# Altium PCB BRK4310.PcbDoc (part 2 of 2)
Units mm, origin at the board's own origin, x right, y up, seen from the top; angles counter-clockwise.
Board outline 150 x 90 mm, 2 copper layers (Top Layer, Bottom Layer), stack 1.646 mm thick; 21 components, 213 nets, 662 pads, 124 vias.
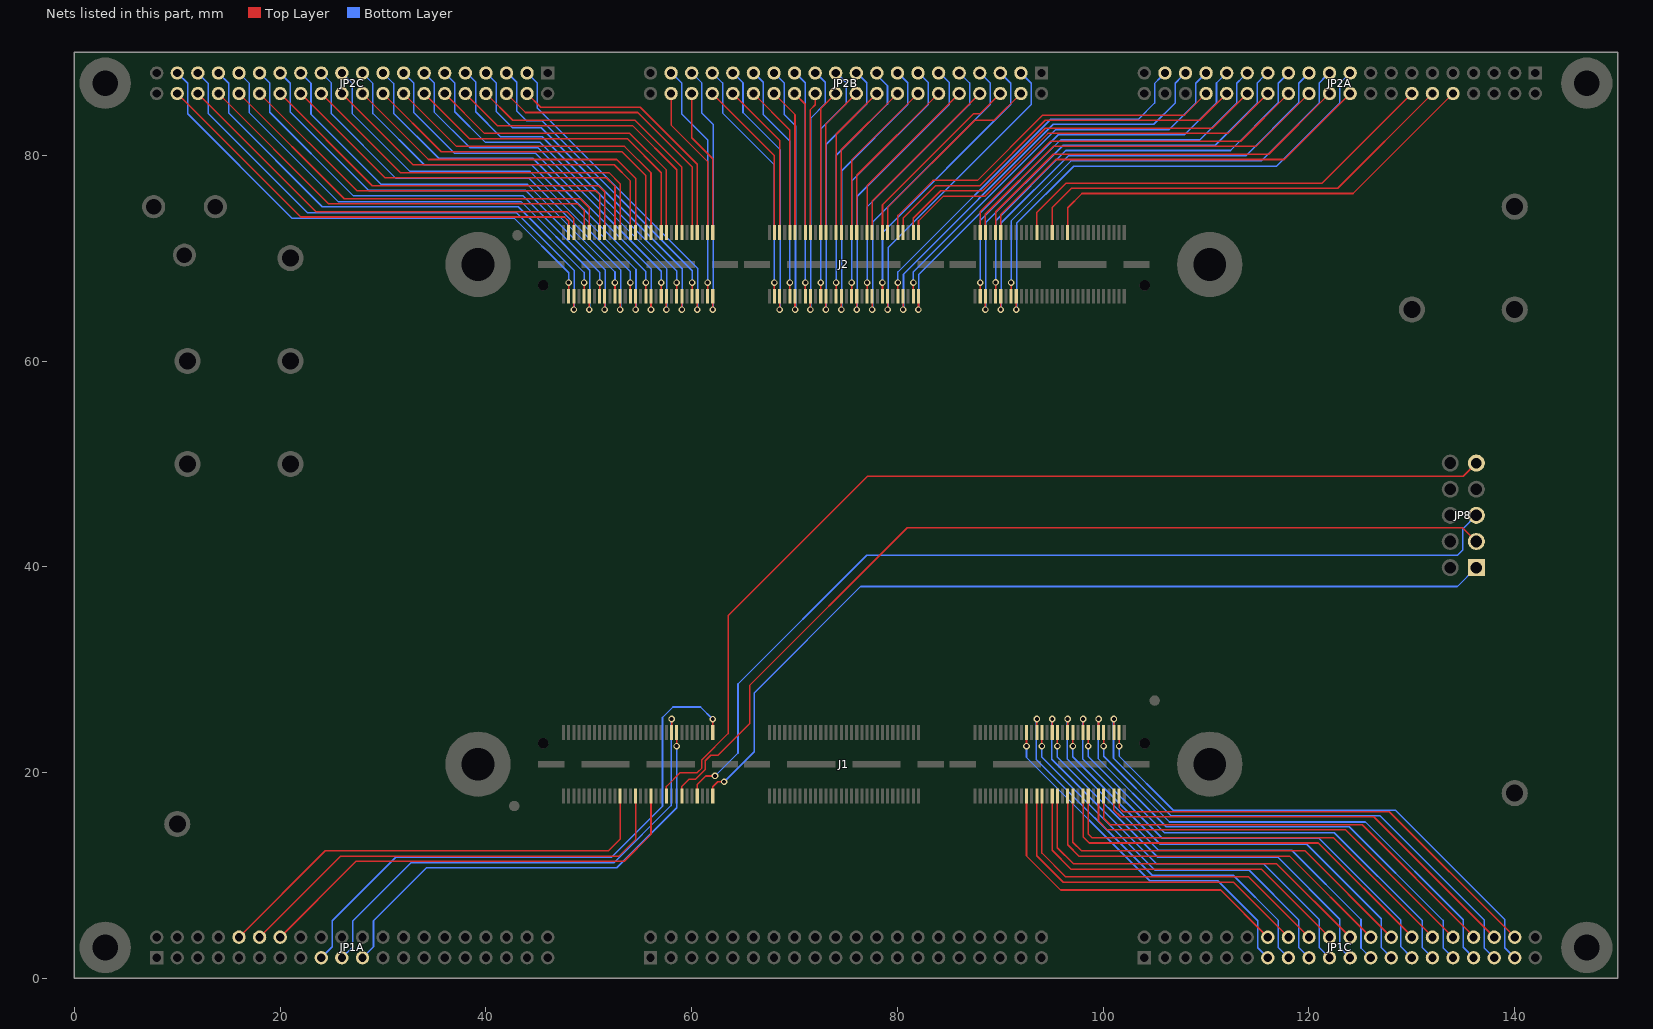
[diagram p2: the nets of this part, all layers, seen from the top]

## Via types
v1: diameter 0.635, hole 0.381, Top Layer to Bottom Layer, tented both sides, 112 vias
v2: diameter 0.889, hole 0.508, Top Layer to Bottom Layer, tented both sides, 12 vias

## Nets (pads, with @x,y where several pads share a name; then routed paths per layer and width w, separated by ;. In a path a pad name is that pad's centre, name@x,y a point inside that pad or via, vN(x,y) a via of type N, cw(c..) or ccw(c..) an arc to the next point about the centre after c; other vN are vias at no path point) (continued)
J1_141: J1.141 JP1C.13 | length 35.5
  Top Layer w0.152: v1(92.545,22.573) J1.141@92.545,23.905
  Bottom Layer w0.152: v1(92.545,22.573) 92.545,21.471 104.534,9.482 111.138,9.482 115.024,5.596 115.024,2.976 JP1C.13@116,2
J1_142: J1.142 JP1C.14 | length 32.6
  Top Layer w0.152: J1.142@92.545,17.725 92.545,11.893 95.856,8.582 111.418,8.582 JP1C.14@116,4
J1_145: J1.145 JP1C.15 | length 39.3
  Top Layer w0.152: J1.145@93.545,23.905 v1(93.545,25.206)
  Bottom Layer w0.152: v1(93.545,25.206) 93.499,25.16 93.499,21.279 104.763,10.015 112.637,10.015 117.031,5.621 117.031,2.969 JP1C.15@118,2
J1_146: J1.146 JP1C.16 | length 33.5
  Top Layer w0.152: J1.146@93.545,17.725 93.545,11.909 96.11,9.344 112.656,9.344 JP1C.16@118,4
J1_147: J1.147 JP1C.17 | length 38
  Top Layer w0.152: v1(94.045,22.573) J1.147@94.045,23.905
  Bottom Layer w0.152: v1(94.045,22.573) 94.045,21.495 105.042,10.498 114.186,10.498 118.987,5.697 118.987,3.013 JP1C.17@120,2
J1_148: J1.148 JP1C.18 | length 34.9
  Top Layer w0.152: J1.148@94.045,17.725 94.045,12.171 96.364,9.852 114.148,9.852 JP1C.18@120,4
J1_151: J1.151 JP1C.19 | length 41.8
  Top Layer w0.152: J1.151@95.045,23.905 v1(95.045,25.206)
  Bottom Layer w0.152: v1(95.045,25.206) 94.999,25.16 94.999,21.303 105.169,11.133 115.583,11.133 120.993,5.723 120.993,3.007 JP1C.19@122,2
J1_152: J1.152 JP1C.20 | length 35.7
  Top Layer w0.152: J1.152@95.045,17.725 95.045,12.441 96.872,10.614 115.386,10.614 JP1C.20@122,4
J1_153: J1.153 JP1C.21 | length 40.5
  Top Layer w0.152: v1(95.545,22.573) J1.153@95.545,23.905
  Bottom Layer w0.152: v1(95.545,22.573) 95.545,21.519 105.296,11.768 116.98,11.768 123,5.748 123,3 JP1C.21@124,2
J1_154: J1.154 JP1C.22 | length 37.1
  Top Layer w0.152: J1.154@95.545,17.725 95.545,12.703 97.126,11.122 116.878,11.122 JP1C.22@124,4
J1_157: J1.157 JP1C.23 | length 44.3
  Top Layer w0.152: J1.157@96.545,23.905 v1(96.545,25.206)
  Bottom Layer w0.152: v1(96.545,25.206) 96.499,25.16 96.499,21.327 105.372,12.454 118.326,12.454 125.057,5.723 125.057,2.943 JP1C.23@126,2
J1_158: J1.158 JP1C.24 | length 37.9
  Top Layer w0.152: J1.158@96.545,17.725 96.545,12.973 97.634,11.884 118.116,11.884 JP1C.24@126,4
J1_159: J1.159 JP1C.25 | length 43.1
  Top Layer w0.152: v1(97.045,22.573) J1.159@97.045,23.905
  Bottom Layer w0.152: v1(97.045,22.573) 97.045,21.543 105.55,13.038 119.774,13.038 127.013,5.799 127.013,2.987 JP1C.25@128,2
J1_160: J1.160 JP1C.26 | length 39.3
  Top Layer w0.152: J1.160@97.045,17.725 97.045,13.235 97.888,12.392 119.608,12.392 JP1C.26@128,4
J1_163: J1.163 JP1C.27 | length 46.7
  Top Layer w0.152: J1.163@98.045,23.905 v1(98.045,25.206)
  Bottom Layer w0.152: v1(98.045,25.206) 97.999,25.16 97.999,21.351 105.728,13.622 120.968,13.622 128.918,5.672 128.918,3.082 JP1C.27@130,2
J1_164: J1.164 JP1C.28 | length 39.6
  Top Layer w0.152: J1.164@98.045,17.725 98.045,13.759 98.65,13.154 120.903,13.154 129.59,4.467 JP1C.28@129.59,4.2
J1_165: J1.165 JP1C.29 | length 45.4
  Top Layer w0.152: v1(98.545,22.573) J1.165@98.545,23.905
  Bottom Layer w0.152: v1(98.545,22.573) 98.545,21.567 105.956,14.156 122.466,14.156 131.001,5.621 131.001,2.999 JP1C.29@132,2
J1_166: J1.166 JP1C.30 | length 41
  Top Layer w0.152: J1.166@98.545,17.725 98.545,14.021 98.904,13.662 122.376,13.662 131.59,4.448 JP1C.30@131.59,4.2
J1_169: J1.169 JP1C.31 | length 49.2
  Top Layer w0.152: J1.169@99.545,23.905 v1(99.545,25.206)
  Bottom Layer w0.152: v1(99.545,25.206) 99.499,25.16 99.499,21.375 106.134,14.74 123.914,14.74 133.033,5.621 133.033,2.967 JP1C.31@134,2
J1_170: J1.170 JP1C.32 | length 41.6
  Top Layer w0.152: J1.170@99.545,17.725 99.545,15.307 100.428,14.424 123.576,14.424 JP1C.32@134,4
J1_171: J1.171 JP1C.33 | length 48
  Top Layer w0.152: v1(100.045,22.573) J1.171@100.045,23.905
  Bottom Layer w0.152: v1(100.045,22.573) 100.045,21.591 106.439,15.197 125.489,15.197 134.989,5.697 134.989,3.011 JP1C.33@136,2
J1_172: J1.172 JP1C.34 | length 42.6
  Top Layer w0.152: J1.172@100.045,17.725 100.045,15.569 100.682,14.932 125.17,14.932 135.59,4.512 JP1C.34@135.59,4.2
J1_175: J1.175 JP1C.35 | length 51.8
  Top Layer w0.152: J1.175@101.045,23.905 v1(101.045,25.206)
  Bottom Layer w0.152: v1(101.045,25.206) 100.999,25.16 100.999,21.399 106.617,15.781 126.937,15.781 137.046,5.672 137.046,2.954 JP1C.35@138,2
J1_176: J1.176 JP1C.36 | length 43.4
  Top Layer w0.152: J1.176@101.045,17.725 101.045,16.347 101.698,15.694 126.306,15.694 JP1C.36@138,4
J1_177: J1.177 JP1C.37 | length 50.5
  Top Layer w0.152: v1(101.545,22.573) J1.177@101.545,23.905
  Bottom Layer w0.152: v1(101.545,22.573) 101.545,21.615 106.82,16.34 128.41,16.34 139.027,5.723 139.027,2.973 JP1C.37@140,2
J1_178: J1.178 JP1C.38 | length 44.4
  Top Layer w0.152: J1.178@101.545,17.725 101.545,16.609 101.952,16.202 127.811,16.202 139.59,4.423 JP1C.38@139.59,4.2
J2_49: J2.49 JP2A.23 | length 46.8
  Top Layer w0.152: v1(90.045,64.992) J2.49@90.045,66.295
  Bottom Layer w0.152: v1@90.091,65.058 90.091,73.429 96.618,79.956 113.869,79.956 119.012,85.099 119.012,87.003 119.59,87.581 JP2A.23@119.59,88.2
J2_50: J2.50 JP2A.20 | length 40.6
  Top Layer w0.152: J2.50@90.045,72.475 90.045,74.241 95.39,79.586 117.586,79.586 JP2A.20@124,86
J2_51: J2.51 JP2A.25 | length 42.9
  Top Layer w0.152: J2.51@89.545,66.295 v1(89.545,67.645)
  Bottom Layer w0.152: v1(89.545,67.645) 89.545,73.645 96.364,80.464 112.377,80.464 117.005,85.092 117.005,87.003 117.59,87.587 JP2A.25@117.59,88.2
J2_52: J2.52 JP2A.22 | length 39.2
  Top Layer w0.152: J2.52@89.545,72.475 89.545,74.503 95.136,80.094 116.094,80.094 JP2A.22@122,86
J2_55: J2.55 JP2A.27 | length 44.3
  Top Layer w0.152: v1(88.545,64.994) J2.55@88.545,66.295
  Bottom Layer w0.152: v1@88.591,65.04 88.591,73.453 96.11,80.972 110.885,80.972 114.973,85.06 114.973,87.028 115.59,87.645 JP2A.27@115.59,88.2
J2_56: J2.56 JP2A.24 | length 38.1
  Top Layer w0.152: J2.56@88.545,72.475 88.545,74.265 95.136,80.856 114.856,80.856 JP2A.24@120,86
J2_57: J2.57 JP2A.29 | length 40.4
  Top Layer w0.152: J2.57@88.045,66.295 v1(88.045,67.627)
  Bottom Layer w0.152: v1(88.045,67.627) 88.045,73.669 95.856,81.48 109.393,81.48 112.992,85.079 112.992,87.003 113.59,87.601 JP2A.29@113.59,88.2
J2_58: J2.58 JP2A.26 | length 36.8
  Top Layer w0.152: J2.58@88.045,72.475 88.045,74.527 94.882,81.364 113.364,81.364 JP2A.26@118,86
J2_61: J2.61 JP2A.31 | length 43.9
  Top Layer w0.152: v1(82.045,64.994) J2.61@82.045,66.295
  Bottom Layer w0.152: v1@82.091,65.04 82.091,68.439 95.64,81.988 107.901,81.988 111.011,85.098 111.011,87.028 111.59,87.607 JP2A.31@111.59,88.2
J2_62: J2.62 JP2A.28 | length 40.2
  Top Layer w0.152: J2.62@82.045,72.475 82.045,73.607 84.468,76.03 88.532,76.03 94.628,82.126 112.126,82.126 JP2A.28@116,86
J2_63: J2.63 JP2A.33 | length 40
  Top Layer w0.152: J2.63@81.545,66.295 v1(81.545,67.627)
  Bottom Layer w0.152: v1(81.545,67.627) 81.545,68.651 95.39,82.496 106.409,82.496 109.004,85.091 109.004,87.003 109.59,87.588 JP2A.33@109.59,88.2
J2_64: J2.64 JP2A.30 | length 38.9
  Top Layer w0.152: J2.64@81.545,72.475 81.545,73.869 84.214,76.538 88.278,76.538 94.374,82.634 110.634,82.634 JP2A.30@114,86
J2_67: J2.67 JP2A.35 | length 41.4
  Top Layer w0.152: v1(80.545,64.994) J2.67@80.545,66.295
  Bottom Layer w0.152: v1@80.591,65.04 80.591,68.439 95.156,83.004 104.917,83.004 106.998,85.085 106.998,87.003 107.59,87.595 JP2A.35@107.59,88.2
J2_68: J2.68 JP2A.32 | length 37.9
  Top Layer w0.152: J2.68@80.545,72.475 80.545,73.885 83.706,77.046 88.024,77.046 94.374,83.396 109.396,83.396 JP2A.32@112,86
J2_69: J2.69 JP2A.37 | length 37.5
  Top Layer w0.152: J2.69@80.045,66.295 v1(80.045,67.627)
  Bottom Layer w0.152: v1(80.045,67.627) 80.045,68.651 94.906,83.512 103.425,83.512 104.991,85.078 104.991,86.977 105.59,87.576 JP2A.37@105.59,88.2
J2_70: J2.70 JP2A.34 | length 36.5
  Top Layer w0.152: J2.70@80.045,72.475 80.045,74.147 83.452,77.554 87.77,77.554 94.12,83.904 107.904,83.904 JP2A.34@110,86
J2_73: J2.73 JP2B.3 | length 30.9
  Top Layer w0.152: v1(79.045,64.994) J2.73@79.045,66.295
  Bottom Layer w0.152: v1@79.091,65.04 79.091,71.018 93.002,84.93 93.002,87.003 91.805,88.2 JP2B.3@91.59,88.2
J2_74: J2.74 JP2B.4 | length 19.2
  Top Layer w0.152: 79.045,73.236 79.045,74.925 87.516,83.396 89.396,83.396 JP2B.4@92,86
J2_75: J2.75 JP2B.5 | length 27.8
  Top Layer w0.152: J2.75@78.545,66.295 v1(78.545,67.627)
  Bottom Layer w0.152: v1(78.545,67.627) 78.545,72.472 91.021,84.948 91.021,87.003 89.824,88.2 JP2B.5@89.59,88.2
J2_76: J2.76 JP2B.6 | length 18.6
  Top Layer w0.152: J2.76@78.545,72.475 78.545,75.187 87.382,84.024 88.024,84.024 JP2B.6@90,86
J2_79: J2.79 JP2B.7 | length 29.9
  Top Layer w0.152: v1(77.545,64.994) J2.79@77.545,66.295
  Bottom Layer w0.152: v1@77.591,65.04 77.591,73.518 89.015,84.942 89.015,87.028 87.843,88.2 JP2B.7@87.59,88.2
J2_80: J2.80 JP2B.8 | length 17.9
  Top Layer w0.152: J2.80@77.545,72.475 77.545,75.545 JP2B.8@88,86
J2_81: J2.81 JP2B.9 | length 26.8
  Top Layer w0.152: J2.81@77.045,66.295 v1(77.045,67.627)
  Bottom Layer w0.152: v1(77.045,67.627) 77.045,74.972 87.008,84.935 87.008,87.028 85.836,88.2 JP2B.9@85.59,88.2
J2_82: J2.82 JP2B.10 | length 17.2
  Top Layer w0.152: J2.82@77.045,72.475 77.045,77.045 JP2B.10@86,86
J2_85: J2.85 JP2B.11 | length 28.9
  Top Layer w0.152: v1(76.045,64.994) J2.85@76.045,66.295
  Bottom Layer w0.152: v1@76.091,65.04 76.091,76.018 85.027,84.954 85.027,87.079 83.906,88.2 JP2B.11@83.59,88.2
J2_86: J2.86 JP2B.12 | length 16.8
  Top Layer w0.152: J2.86@76.045,72.475 76.045,78.045 JP2B.12@84,86
J2_87: J2.87 JP2B.13 | length 25.7
  Top Layer w0.152: J2.87@75.545,66.295 v1(75.545,67.627)
  Bottom Layer w0.152: v1(75.545,67.627) 75.545,77.472 82.995,84.922 82.995,87.079 81.874,88.2 JP2B.13@81.59,88.2
J2_88: J2.88 JP2B.14 | length 16.2
  Top Layer w0.152: J2.88@75.545,72.475 75.545,79.545 JP2B.14@82,86
J2_91: J2.91 JP2B.15 | length 27.9
  Top Layer w0.152: v1(74.545,64.994) J2.91@74.545,66.295
  Bottom Layer w0.152: v1@74.591,65.04 74.591,78.503 81.014,84.926 81.014,87.054 79.867,88.2 JP2B.15@79.59,88.2
J2_92: J2.92 JP2B.16 | length 15.8
  Top Layer w0.152: J2.92@74.545,72.475 74.545,80.545 JP2B.16@80,86
J2_93: J2.93 JP2B.17 | length 24.6
  Top Layer w0.152: J2.93@74.045,66.295 v1(74.045,67.627)
  Bottom Layer w0.152: v1(74.045,67.627) 74.045,79.989 79.032,84.976 79.032,86.758 JP2B.17@77.59,88.2
J2_94: J2.94 JP2B.18 | length 15.2
  Top Layer w0.152: J2.94@74.045,72.475 74.045,82.045 JP2B.18@78,86
J2_97: J2.97 JP2B.19 | length 26.9
  Top Layer w0.152: v1(73.045,64.994) J2.97@73.045,66.295
  Bottom Layer w0.152: v1@73.091,65.04 73.091,81.067 77.026,85.002 77.026,87.054 75.879,88.2 JP2B.19@75.59,88.2
J2_98: J2.98 JP2B.20 | length 14.7
  Top Layer w0.152: J2.98@73.045,72.475 73.045,83.045 JP2B.20@76,86
J2_99: J2.99 JP2B.21 | length 23.7
  Top Layer w0.152: J2.99@72.545,66.295 v1(72.545,67.627)
  Bottom Layer w0.152: v1(72.545,67.627) 72.545,82.553 75.019,85.027 75.019,87.054 73.873,88.2 JP2B.21@73.59,88.2
J2_100: J2.100 JP2B.22 | length 14.1
  Top Layer w0.152: J2.100@72.545,72.475 72.545,84.545 JP2B.22@74,86
J2_103: J2.103 JP2B.23 | length 25.8
  Top Layer w0.152: v1(71.545,64.994) J2.103@71.545,66.295
  Bottom Layer w0.152: v1@71.591,65.04 71.591,83.631 72.987,85.027 72.987,87.104 71.892,88.2 JP2B.23@71.59,88.2
J2_104: J2.104 JP2B.24 | length 13.7
  Top Layer w0.152: J2.104@71.545,72.475 71.545,84.443 72,84.898 JP2B.24@72,86
J2_105: J2.105 JP2B.25 | length 22.7
  Top Layer w0.152: J2.105@71.045,66.295 v1(71.045,67.627)
  Bottom Layer w0.152: JP2B.25@69.59,88.2 69.885,88.2 71.045,87.04 v1(71.045,67.627)
J2_106: J2.106 JP2B.26 | length 14
  Top Layer w0.152: JP2B.26@70,86 71.045,84.955 J2.106@71.045,72.475
J2_109: J2.109 JP2B.27 | length 25.6
  Top Layer w0.152: v1(70.045,64.994) J2.109@70.045,66.295
  Bottom Layer w0.152: JP2B.27@67.59,88.2 67.828,88.2 68.999,87.028 68.999,83.953 70.091,82.861 v1@70.091,65.04
J2_110: J2.110 JP2B.28 | length 14.4
  Top Layer w0.152: JP2B.28@68,86 70.045,83.955 J2.110@70.045,72.475
J2_111: J2.111 JP2B.29 | length 23.7
  Top Layer w0.152: J2.111@69.545,66.295 v1(69.545,67.627)
  Bottom Layer w0.152: JP2B.29@65.59,88.2 65.872,88.2 66.967,87.104 66.967,83.953 69.545,81.375 v1(69.545,67.627)
J2_112: J2.112 JP2B.30 | length 15
  Top Layer w0.152: JP2B.30@66,86 69.545,82.455 J2.112@69.545,72.475
J2_115: J2.115 JP2B.31 | length 26.7
  Top Layer w0.152: v1(68.545,64.994) J2.115@68.545,66.295
  Bottom Layer w0.152: JP2B.31@63.59,88.2 63.84,88.2 64.986,87.054 64.986,84.156 68.591,80.551 68.591,65.04 v1(68.545,64.994)
J2_116: J2.116 JP2B.32 | length 15.4
  Top Layer w0.152: JP2B.32@64,86 68.545,81.455 J2.116@68.545,72.475
J2_117: J2.117 JP2B.33 | length 24.7
  Top Layer w0.152: J2.117@68.045,66.295 v1(68.045,67.627)
  Bottom Layer w0.152: JP2B.33@61.59,88.2 61.833,88.2 63.005,87.028 63.005,84.105 68.045,79.065 v1(68.045,67.627)
J2_118: J2.118 JP2B.34 | length 16
  Top Layer w0.152: JP2B.34@62,86 68.045,79.955 J2.118@68.045,72.475
J2_121: J2.121 JP2B.35 | length 25.7
  Top Layer w0.152: v1(62.045,64.994) J2.121@62.045,66.295
  Bottom Layer w0.152: JP2B.35@59.59,88.2 59.827,88.2 60.998,87.028 60.998,84.08 62.091,82.987 62.091,65.04 v1(62.045,64.994)
J2_122: J2.122 JP2B.36 | length 14.4
  Top Layer w0.152: JP2B.36@60,86 60,81.702 62.045,79.657 J2.122@62.045,72.475
J2_123: J2.123 JP2B.37 | length 23.7
  Top Layer w0.152: J2.123@61.545,66.295 v1(61.545,67.627)
  Bottom Layer w0.152: JP2B.37@57.59,88.2 57.871,88.2 59.017,87.054 59.017,84.029 61.545,81.501 v1(61.545,67.627)
J2_124: J2.124 JP2B.38 | length 15
  Top Layer w0.152: JP2B.38@58,86 58,82.94 61.545,79.395 J2.124@61.545,72.475
J2_127: J2.127 JP2C.3 | length 31.7
  Top Layer w0.152: v1(60.545,64.994) J2.127@60.545,66.295
  Bottom Layer w0.152: JP2C.3@43.59,88.2 43.825,88.2 44.996,87.028 44.996,84.588 60.591,68.993 60.591,65.04 v1(60.545,64.994)
J2_128: J2.128 JP2C.4 | length 26
  Top Layer w0.152: JP2C.4@44,86 45.334,84.666 55.004,84.666 60.545,79.125 J2.128@60.545,72.475
J2_129: J2.129 JP2C.5 | length 30.6
  Top Layer w0.152: J2.129@60.045,66.295 v1(60.045,67.627)
  Bottom Layer w0.152: JP2C.5@41.59,88.2 41.894,88.2 42.99,87.104 42.99,84.308 43.964,83.334 45.488,83.334 60.045,68.777 v1(60.045,67.627)
J2_130: J2.130 JP2C.6 | length 27.4
  Top Layer w0.152: JP2C.6@42,86 43.842,84.158 54.75,84.158 60.045,78.863 J2.130@60.045,72.475
J2_133: J2.133 JP2C.7 | length 34.4
  Top Layer w0.152: v1(59.045,64.994) J2.133@59.045,66.295
  Bottom Layer w0.152: JP2C.7@39.59,88.2 39.837,88.2 41.009,87.028 41.009,84.257 42.592,82.674 45.386,82.674 59.091,68.969 59.091,65.04 v1(59.045,64.994)
J2_134: J2.134 JP2C.8 | length 28.4
  Top Layer w0.152: JP2C.8@40,86 42.604,83.396 54.496,83.396 59.045,78.847 J2.134@59.045,72.475
J2_135: J2.135 JP2C.9 | length 33.2
  Top Layer w0.152: J2.135@58.545,66.295 v1(58.545,67.627)
  Bottom Layer w0.152: JP2C.9@37.59,88.2 37.932,88.2 39.002,87.13 39.002,84.232 41.424,81.81 45.488,81.81 58.545,68.753 v1(58.545,67.627)
J2_136: J2.136 JP2C.10 | length 29.7
  Top Layer w0.152: JP2C.10@38,86 41.112,82.888 54.242,82.888 58.545,78.585 J2.136@58.545,72.475
J2_139: J2.139 JP2C.11 | length 36.8
  Top Layer w0.152: v1(57.545,64.994) J2.139@57.545,66.295
  Bottom Layer w0.152: JP2C.11@35.59,88.2 JP2C.11@35.895,87.895 ; JP2C.11@36,88 36.97,87.03 36.97,84.232 39.951,81.251 45.285,81.251 57.591,68.945 57.591,65.04 v1(57.545,64.994)
J2_140: J2.140 JP2C.12 | length 30.7
  Top Layer w0.152: JP2C.12@36,86 39.874,82.126 53.988,82.126 57.545,78.569 J2.140@57.545,72.475
J2_141: J2.141 JP2C.13 | length 35.6
  Top Layer w0.152: J2.141@57.045,66.295 v1(57.045,67.627)
  Bottom Layer w0.152: JP2C.13@33.59,88.2 JP2C.13@33.895,87.895 ; JP2C.13@34,88 34.963,87.037 34.963,84.207 38.452,80.718 45.056,80.718 57.045,68.729 v1(57.045,67.627)
J2_142: J2.142 JP2C.14 | length 32.1
  Top Layer w0.152: JP2C.14@34,86 38.382,81.618 53.734,81.618 57.045,78.307 J2.142@57.045,72.475
J2_145: J2.145 JP2C.15 | length 39.3
  Top Layer w0.152: v1(56.045,64.994) J2.145@56.045,66.295
  Bottom Layer w0.152: JP2C.15@31.59,88.2 JP2C.15@31.895,87.895 ; JP2C.15@32,88 32.98,87.02 32.98,84.158 36.953,80.185 44.827,80.185 56.091,68.921 56.091,65.04 v1(56.045,64.994)
J2_146: J2.146 JP2C.16 | length 33.1
  Top Layer w0.152: JP2C.16@32,86 37.144,80.856 53.48,80.856 56.045,78.291 J2.146@56.045,72.475
J2_147: J2.147 JP2C.17 | length 38.1
  Top Layer w0.152: J2.147@55.545,66.295 v1(55.545,67.627)
  Bottom Layer w0.152: JP2C.17@29.59,88.2 JP2C.17@29.895,87.895 ; JP2C.17@30,88 31.026,86.974 31.026,84.08 35.404,79.702 44.548,79.702 55.545,68.705 v1(55.545,67.627)
J2_148: J2.148 JP2C.18 | length 34.4
  Top Layer w0.152: JP2C.18@30,86 35.652,80.348 53.226,80.348 55.545,78.029 J2.148@55.545,72.475
J2_151: J2.151 JP2C.19 | length 41.4
  Top Layer w0.152: v1(54.545,64.994) J2.151@54.545,66.295
  Bottom Layer w0.152: JP2C.19@28,88 29.02,86.98 29.02,84.054 34.007,79.067 44.421,79.067 54.591,68.897 54.591,65.04 v1(54.545,64.994)
J2_152: J2.152 JP2C.20 | length 35.2
  Top Layer w0.152: JP2C.20@28,86 34.414,79.586 52.718,79.586 54.545,77.759 J2.152@54.545,72.475
J2_153: J2.153 JP2C.21 | length 40.2
  Top Layer w0.152: J2.153@54.045,66.295 v1(54.045,67.627)
  Bottom Layer w0.152: JP2C.21@26,88 26.988,87.012 26.988,84.054 32.61,78.432 44.294,78.432 54.045,68.681 v1(54.045,67.627)
J2_154: J2.154 JP2C.22 | length 36.6
  Top Layer w0.152: JP2C.22@26,86 32.922,79.078 52.464,79.078 54.045,77.497 J2.154@54.045,72.475
J2_157: J2.157 JP2C.23 | length 44
  Top Layer w0.152: v1(53.045,64.994) J2.157@53.045,66.295
  Bottom Layer w0.152: JP2C.23@24,88 24.981,87.019 24.981,84.029 31.264,77.746 44.218,77.746 53.091,68.873 53.091,65.04 v1(53.045,64.994)
J2_158: J2.158 JP2C.24 | length 37.4
  Top Layer w0.152: JP2C.24@24,86 31.684,78.316 51.956,78.316 53.045,77.227 J2.158@53.045,72.475
J2_159: J2.159 JP2C.25 | length 42.7
  Top Layer w0.152: J2.159@52.545,66.295 v1(52.545,67.627)
  Bottom Layer w0.152: JP2C.25@22,88 23,87 23,83.978 29.816,77.162 44.04,77.162 52.545,68.657 v1(52.545,67.627)
J2_160: J2.160 JP2C.26 | length 38.8
  Top Layer w0.152: JP2C.26@22,86 30.192,77.808 51.702,77.808 52.545,76.965 J2.160@52.545,72.475
J2_163: J2.163 JP2C.27 | length 46.3
  Top Layer w0.152: v1(51.545,64.994) J2.163@51.545,66.295
  Bottom Layer w0.152: JP2C.27@20,88 20.993,87.007 20.993,84.207 28.622,76.578 43.862,76.578 51.591,68.849 51.591,65.04 v1(51.545,64.994)
J2_164: J2.164 JP2C.28 | length 39.5
  Top Layer w0.152: JP2C.28@20,86 28.954,77.046 50.94,77.046 51.545,76.441 J2.164@51.545,72.475
J2_165: J2.165 JP2C.29 | length 45.1
  Top Layer w0.152: J2.165@51.045,66.295 v1(51.045,67.627)
  Bottom Layer w0.152: JP2C.29@18,88 18.987,87.013 18.987,84.181 27.124,76.044 43.634,76.044 51.045,68.633 v1(51.045,67.627)
J2_166: J2.166 JP2C.30 | length 40.8
  Top Layer w0.152: JP2C.30@18,86 27.462,76.538 50.686,76.538 51.045,76.179 J2.166@51.045,72.475
J2_169: J2.169 JP2C.31 | length 48.9
  Top Layer w0.152: v1(50.045,64.994) J2.169@50.045,66.295
  Bottom Layer w0.152: JP2C.31@16,88 16.98,87.02 16.98,84.156 25.676,75.46 43.456,75.46 50.091,68.825 50.091,65.04 v1(50.045,64.994)
J2_170: J2.170 JP2C.32 | length 41.1
  Top Layer w0.152: JP2C.32@16,86 26.224,75.776 49.162,75.776 50.045,74.893 J2.170@50.045,72.475
J2_171: J2.171 JP2C.33 | length 47.6
  Top Layer w0.152: J2.171@49.545,66.295 v1(49.545,67.627)
  Bottom Layer w0.152: JP2C.33@14,88 14.999,87.001 14.999,84.105 24.101,75.003 43.151,75.003 49.545,68.609 v1(49.545,67.627)
J2_172: J2.172 JP2C.34 | length 42.4
  Top Layer w0.152: JP2C.34@14,86 24.732,75.268 48.908,75.268 49.545,74.631 J2.172@49.545,72.475
J2_175: J2.175 JP2C.35 | length 51.4
  Top Layer w0.152: v1(48.545,64.994) J2.175@48.545,66.295
  Bottom Layer w0.152: JP2C.35@12,88 12.992,87.008 12.992,84.08 22.653,74.419 42.973,74.419 48.591,68.801 48.591,65.04 v1(48.545,64.994)
J2_176: J2.176 JP2C.36 | length 43
  Top Layer w0.152: JP2C.36@12,86 23.494,74.506 47.892,74.506 48.545,73.853 J2.176@48.545,72.475
J2_177: J2.177 JP2C.37 | length 50.1
  Top Layer w0.152: J2.177@48.045,66.295 v1(48.045,67.627)
  Bottom Layer w0.152: JP2C.37@10,88 11.011,86.989 11.011,84.029 21.18,73.86 42.77,73.86 48.045,68.585 v1(48.045,67.627)
J2_178: J2.178 JP2C.38 | length 44.3
  Top Layer w0.152: JP2C.38@10,86 22.002,73.998 47.638,73.998 48.045,73.591 J2.178@48.045,72.475
JTAG_TCK_1P8: J1.60 JP8.1 | length 87.3
  Top Layer w0.152: J1.60@62.045,17.725 62.045,18.631 62.522,19.109 v1(63.157,19.109)
  Bottom Layer w0.152: v1(63.157,19.109) 66.078,22.03 66.078,27.745 76.416,38.082 134.432,38.082 JP8.1@136.27,39.92
JTAG_TDI_1P8: J1.42 JP8.9 | length 99.8
  Top Layer w0.152: J1.42@57.545,17.725 57.545,18.652 58.865,19.972 60.516,19.972 60.998,20.455 60.998,21.247 63.538,23.787 63.538,35.243 77.097,48.801 134.991,48.801 JP8.9@136.27,50.08
JTAG_TDO_1P8: J1.48 JP8.3 | length 91.8
  Top Layer w0.152: J1.48@59.045,17.725 59.045,18.654 59.754,19.363 60.389,19.363 61.329,20.302 61.329,21.146 61.862,21.68 62.553,21.68 65.659,24.785 65.659,28.499 80.958,43.797 134.933,43.797 JP8.3@136.27,42.46
JTAG_TMS_1P8: J1.54 JP8.5 | length 92.9
  Top Layer w0.152: J1.54@60.545,17.725 60.545,18.833 61.379,19.667 v1(62.268,19.667) v1@62.319,19.718
  Bottom Layer w0.152: v1(62.268,19.667) 64.504,21.903 64.504,28.608 77.026,41.13 134.43,41.13 134.963,41.664 134.963,43.693 JP8.5@136.27,45
OVP: J1.59 JP1A.17 | length 56.5
  Top Layer w0.152: J1.59@62.045,23.905 v1(62.045,25.19)
  Bottom Layer w0.152: JP1A.17@24,2 25.073,3.073 25.073,5.596 31.245,11.768 52.21,11.768 57.163,16.721 57.163,25.357 58.179,26.373 60.862,26.373 v1(62.045,25.19)
PLL1_CLKOUT_N: J1.45 JP1A.21 | length 45.4
  Top Layer w0.152: v1(58.545,22.573) J1.45@58.545,23.905
  Bottom Layer w0.152: JP1A.21@28,2 29.073,3.073 29.073,5.596 34.229,10.752 52.718,10.752 58.545,16.579 v1(58.545,22.573)
PLL1_CLKOUT_P: J1.43 JP1A.19 | length 49.3
  Top Layer w0.152: J1.43@58.045,23.905 v1(58.045,25.206)
  Bottom Layer w0.152: JP1A.19@26,2 27.073,3.073 27.073,5.596 32.737,11.26 52.464,11.26 57.999,16.795 v1@57.999,25.16
PLL4_CLKOUT_N: J2.45 JP2A.21 | length 45.4
  Top Layer w0.152: J2.45@91.045,66.295 v1(91.045,67.627)
  Bottom Layer w0.152: v1(91.045,67.627) 91.045,73.621 96.872,79.448 115.361,79.448 121.019,85.105 121.019,87.054 121.59,87.625 JP2A.21@121.59,88.2
PLL4_CLKOUT_P: J2.43 JP2A.19 | length 49.3
  Top Layer w0.152: v1(91.545,64.994) J2.43@91.545,66.295
  Bottom Layer w0.152: v1@91.591,65.04 91.591,73.405 97.126,78.94 116.853,78.94 123,85.087 123,87.028 123.59,87.618 JP2A.19@123.59,88.2
X_VS0: J1.24 JP1A.10 | length 45.2
  Top Layer w0.152: JP1A.10@16,4 24.392,12.392 51.914,12.392 53.045,13.523 J1.24@53.045,17.725
X_VS1: J1.30 JP1A.12 | length 44.7
  Top Layer w0.152: JP1A.12@18,4 25.884,11.884 52.93,11.884 54.545,13.499 J1.30@54.545,17.725
X_VS2: J1.36 JP1A.14 | length 43.9
  Top Layer w0.152: JP1A.14@20,4 27.376,11.376 53.438,11.376 56.045,13.983 J1.36@56.045,17.725
Y_VS0: J2.24 JP2A.10 | length 44.5
  Top Layer w0.152: J2.24@96.545,72.475 96.545,74.899 97.93,76.284 124.284,76.284 JP2A.10@134,86
Y_VS1: J2.30 JP2A.12 | length 44
  Top Layer w0.152: J2.30@95.045,72.475 95.045,74.923 96.914,76.792 122.792,76.792 JP2A.12@132,86
Y_VS2: J2.36 JP2A.14 | length 43.2
  Top Layer w0.152: J2.36@93.545,72.475 93.545,74.439 96.406,77.3 121.3,77.3 JP2A.14@130,86
pads on no net: J1.1 J1.2 J1.3 J1.4 J1.7 J1.8 J1.9 J1.10 J1.13 J1.14 J1.15 J1.16 J1.19 J1.20 J1.21 J1.22 J1.25 J1.26 J1.27 J1.28 J1.31 J1.32 J1.33 J1.34 J1.37 J1.38 J1.39 J1.40 J1.41 J1.44 J1.46 J1.47 J1.53 J1.MH J2.1 J2.2 J2.3 J2.4 J2.7 J2.8 J2.9 J2.10 J2.13 J2.14 J2.15 J2.16 J2.19 J2.20 J2.21 J2.22 J2.25 J2.26 J2.27 J2.28 J2.31 J2.32 J2.33 J2.34 J2.37 J2.38 J2.39 J2.40 J2.44 J2.46 J2.47 J2.53 J2.54 J2.60 J2.MH JP1A.15 JP1A.16 JP1A.18 JP1A.36 JP1A.38 JP2A.4 JP2A.6 JP2A.36 JP2A.38 JP8.6 JP8.7 JP8.8 P1.3

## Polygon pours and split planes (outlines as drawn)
DGND on Top Layer "DGND" (solid, remove dead copper, pour order 3): 149.5,89.5 149.5,0.5 0.5,0.5 0.5,89.5
+3.3VDD on Bottom Layer "+3.3V" (solid, remove dead copper, pour order 1000): 149.5,0.5 149.5,89.5 0.5,89.5 0.5,0.5
+VDC on Bottom Layer "+VDC" (solid, pour order 5): 101.74,71.712 99.2,71.712 99.2,64.6 99.2,62.822 96.914,60.536 32.144,60.536 15.888,76.792 15.634,77.046 10.808,77.046 10.808,73.236 27.572,56.472 97.422,56.472 97.93,56.472 100.724,59.266 101.74,60.282 101.74,71.712

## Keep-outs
Keep-Out Layer:
  the board outline again, w0.178

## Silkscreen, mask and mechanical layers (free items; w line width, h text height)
Top Overlay:
  lines w0.203: 34.8,15.1 34.8,75.1 114.8,75.1 114.8,15.1 34.8,15.1
  text "DGND" at 126.378,49.614 h1.02
  text "TDI" at 140.602,49.614 h1.02
  text "TMS" at 140.602,44.534 h1.02
  text "+1.8V" at 125.616,41.994 h1.02
  text "TDO" at 140.602,41.994 h1.02
  text "DGND" at 126.378,39.454 h1.02
  text "TCK" at 140.602,39.454 h1.02
  text "USB Connector" at 32.728,38.87 h1.02 r270
  text "ALTERA JTAG" at 128.156,27.516 h1.27
  text "BRK4310" at 17.374,18.618 h1.02
  text "20140103" at 17.144,16.644 h1.02
Top Solder:
  the board outline again, w0.025
Mechanical 2:
  the board outline again, w0.203
Drill Drawing:
  lines w0.15: 90.774,-22.758 171.976,-22.758 ; 90.774,-19.943 171.976,-19.943 ; 89.25,-44.6 ccw(c90.15,-44.6) 90.15,-45.5 172.6,-45.5 ccw(c172.6,-44.6) 173.5,-44.6 173.5,-12.4 ccw(c172.6,-12.4) 172.6,-11.5 90.15,-11.5 ccw(c90.15,-12.4) 89.25,-12.4 89.25,-44.6
  text ":::" at 49,91 h1.27
  text ":::" at 98,91 h1.27
  text ":::" at -2,66 h1.27 r270
  text ":::" at 151,66 h1.27 r270
  text ":::" at -1,30 h1.27 r90
  text ":::" at 152,30 h1.27 r90
  text ".LEGEND" at 156,2 h1.27
  text ":::" at 48.603,-1.975 h1.27
  text ":::" at 98,-2 h1.27
  text "NOTES" at 1.629,-8.71 h1.27
  text "1. MATERIAL SELECTION:" at 1.629,-11.25 h1.27
  text "2-LAYER, 370HR, 0.062\" +/- 0.005 THICK" at 4.804,-13.155 h1.27
  text "SURFACE FINISH: ENIG (ELECTROLESS NICKEL, IMMERSION GOLD)" at 4.804,-15.06 h1.27
  text "Layer Stack Up Detail for: BRK4310.PcbDoc" at 90.774,-17.207 h1.95
  text "2. SOLDER RESIST: GREEN LPI" at 1.629,-18.235 h1.27
  text "Layer" at 90.774,-20.993 h0.65
  text "Gerber" at 108.203,-20.993 h0.65
  text "Copper" at 116.988,-20.993 h0.65
  text "Dielectric" at 126.834,-20.993 h0.65
  text "Dielectric" at 137.135,-20.993 h0.65
  text "Dielectric" at 150.065,-20.993 h0.65
  text "Dielectric" at 160.366,-20.993 h0.65
  text "3. SILKSCREEN: WHITE / DO NOT REMOVE OVER TENTED VIAS." at 1.629,-21.41 h1.27
  text "Name" at 90.774,-22.293 h0.65
  text "Document" at 108.203,-22.293 h0.65
  text "Thickness" at 116.988,-22.293 h0.65
  text "Height" at 126.834,-22.293 h0.65
  text "Material" at 137.135,-22.293 h0.65
  text "Constant" at 150.065,-22.293 h0.65
  text "Type" at 160.366,-22.293 h0.65
  text "4. LOT CODE IDENTIFICATION: ADD TO SILKSCREEN" at 1.629,-24.585 h1.27
  text "Top Solder Mask" at 90.774,-25.032 h0.9
  text "(.GTS)" at 108.203,-25.032 h0.9
  text "0.0102mm" at 126.834,-25.032 h0.9
  text "Solder Resist" at 137.135,-25.032 h0.9
  text "3.50" at 150.065,-25.032 h0.9
  text "5. DRILL SIZES ARE FINISHED SIZE AFTER PLATING." at 1.629,-27.76 h1.27
  text "Top Layer" at 90.774,-29.428 h0.9
  text "(.GTL)" at 108.203,-29.428 h0.9
  text "0.0356mm" at 116.988,-29.428 h0.9
  text "6. ELECTRICAL BARE BOARD TEST REQUIRED" at 1.629,-30.935 h1.27
  text "1.5748mm" at 126.834,-31.627 h0.9
  text "FR-4" at 137.135,-31.627 h0.9
  text "4.80" at 150.065,-31.627 h0.9
  text "Core" at 160.366,-31.627 h0.9
  text "Bottom Layer" at 90.774,-33.825 h0.9
  text "(.GBL)" at 108.203,-33.825 h0.9
  text "0.0356mm" at 116.988,-33.825 h0.9
  text "7. FABRICATE TO MEET EU ROHS DIRECTIVE" at 1.629,-34.11 h1.27
  text "8. PANELIZATION:" at 1.629,-37.169 h1.27
  text "Bottom Solder Mask" at 90.774,-38.222 h0.9
  text "(.GBS)" at 108.203,-38.222 h0.9
  text "0.0102mm" at 126.834,-38.222 h0.9
  text "Solder Resist" at 137.135,-38.222 h0.9
  text "3.50" at 150.065,-38.222 h0.9
  text "2-PIECES PER PANEL" at 4.804,-39.074 h1.27
  text "0.1-IN RAILS ON ALL SIDES" at 4.804,-40.979 h1.27
  text "0.1-IN TAB ROUTING WITH MOUSE-BITES FOR BOARD SEPARATION" at 4.804,-42.884 h1.27

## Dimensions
3,3 to 3,87 on Mechanical 1
0,90 to 0,0 on Mechanical 1
147,3 to 3,3 on Mechanical 1
150,0 to 0,0 on Mechanical 1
